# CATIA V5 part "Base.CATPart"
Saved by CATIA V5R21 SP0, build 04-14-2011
Part number: Base
Bounding box of the stored display mesh (mm): x -30 to 30, y -60 to 60, z -85 to -20
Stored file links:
  D:\CATIA V5R21 E-RESOURCES\CATIA-V5R21\catia-v5r21-Prts\c12_catia_v5r21_prt\c12_catia_v5r21figr_12-35\Base.CATPart
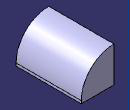
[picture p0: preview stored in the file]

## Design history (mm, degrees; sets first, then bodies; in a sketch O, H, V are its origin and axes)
Body1 (main body)
  Sketch1 on xy-plane, origin (0, 0, 0), H (1, 0, 0), V (0, 1, 0)
    line L1 (30, 60) -> (30, -60)
    line L2 (30, -60) -> (-30, -60)
    line L3 (-30, -60) -> (-30, 60)
    line L4 (-30, 60) -> (30, 60)
    length L2 = 60
    length L3 = 120
    vertical: L1 V, L3 V
    horizontal: L2 H, L4 H
    equidistance: L1 L3 O, L2 L4 O
  Pad1: profile Sketch1, direction (0, 0, -1), length 85, opposite side length -20
  Fillet1: radius 60, on edge [face of Pad1 | face of Pad1]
